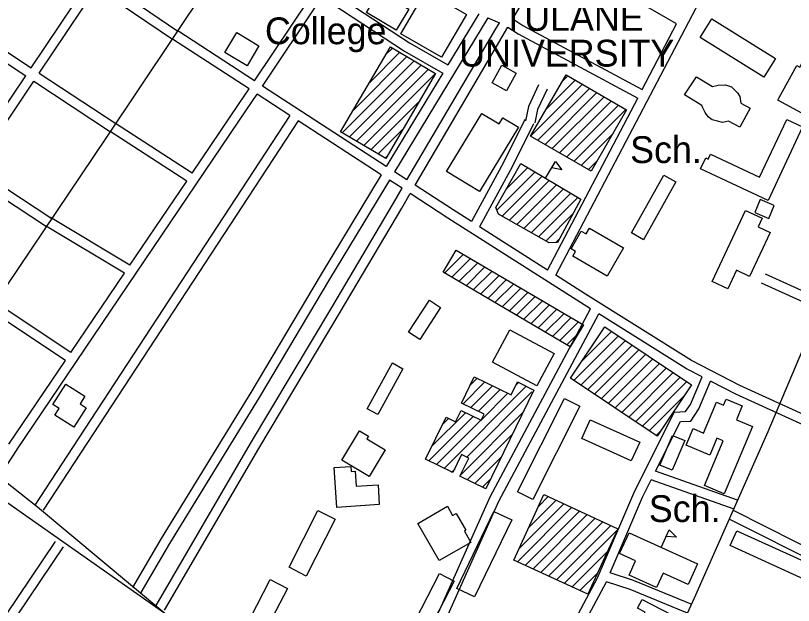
# Model space of a CAD drawing. Extents: x 3651524 to 3689615, y 505651 to 531377.
# Drawn here: x 3663276 to 3665685, y 524140 to 525966 of the extents above; entities that cross this region are included whole.
import ezdxf

# ---------------------------------------------------------------- set-up
doc = ezdxf.new("R2010")
doc.units = 0
for name, color, linetype in [('V-BLDG-IDEN', 7, 'Continuous'), ('V-BLDG-OTLN', 7, 'Continuous'), ('V-ROAD-CNTR', 7, 'Continuous')]:
    doc.layers.add(name, color=color, linetype=linetype)

msp = doc.modelspace()

# ---------------------------------------------------------------- linework, layer by layer
at = {"layer": 'V-BLDG-OTLN'}
for p, q in [((3664372.998, 525758.876), (3664465.933, 525851.811)), ((3664423.428, 525844.661), (3664443.667, 525864.9)), ((3664322.568, 525673.091), (3664488.199, 525838.721)), ((3664287.604, 525602.772), (3664510.465, 525825.632)), ((3664309.87, 525589.683), (3664532.731, 525812.543)), ((3664332.136, 525576.593), (3664554.997, 525799.453)), ((3664354.402, 525563.504), (3664577.263, 525786.364)), ((3664968.187, 525760.105), (3664987.017, 525778.935)), ((3664919.781, 525676.344), (3665009.424, 525765.986)), ((3664871.374, 525592.582), (3665031.83, 525753.037)), ((3664893.78, 525579.633), (3665054.237, 525740.088)), ((3664916.187, 525566.684), (3665076.643, 525727.14)), ((3664938.593, 525553.735), (3665099.049, 525714.191)), ((3664376.668, 525550.415), (3664526.832, 525700.579)), ((3664961, 525540.787), (3665121.456, 525701.243)), ((3664983.406, 525527.838), (3665143.862, 525688.294)), ((3665005.813, 525514.889), (3665166.269, 525675.345)), ((3664398.934, 525537.325), (3664476.401, 525614.792)), ((3665028.219, 525501.94), (3665124.55, 525598.271)), ((3664421.2, 525524.236), (3664425.97, 525529.006)), ((3664917.895, 525462.145), (3664948.648, 525513.665)), ((3665050.626, 525488.991), (3665076.143, 525514.509)), ((3664794.791, 525426.933), (3664862.857, 525494.998)), ((3664766.82, 525363.606), (3664884.996, 525481.783)), ((3664783.193, 525344.624), (3664907.136, 525468.567)), ((3664805.733, 525331.809), (3664929.276, 525455.351)), ((3664828.273, 525318.993), (3664951.416, 525442.136)), ((3664850.812, 525306.177), (3664973.555, 525428.92)), ((3664873.352, 525293.361), (3664995.695, 525415.705)), ((3664895.891, 525280.546), (3665017.835, 525402.489)), ((3664918.431, 525267.73), (3665002.335, 525351.634)), ((3664949.024, 525262.968), (3664961.746, 525275.689)), ((3664604.816, 525168.614), (3664663.039, 525226.837)), ((3664627.088, 525155.531), (3664685.312, 525213.754)), ((3664649.361, 525142.448), (3664707.584, 525200.671)), ((3664671.633, 525129.365), (3664729.856, 525187.588)), ((3664693.905, 525116.282), (3664752.128, 525174.505)), ((3664716.178, 525103.199), (3664774.4, 525161.422)), ((3664738.449, 525090.116), (3664796.673, 525148.339)), ((3664760.721, 525077.033), (3664818.945, 525135.256)), ((3664782.994, 525063.95), (3664841.217, 525122.173)), ((3664805.266, 525050.867), (3664863.49, 525109.09)), ((3664827.538, 525037.784), (3664885.762, 525096.007)), ((3664849.811, 525024.701), (3664908.034, 525082.924)), ((3664872.083, 525011.618), (3664930.307, 525069.841)), ((3664894.355, 524998.535), (3664952.579, 525056.758)), ((3664916.628, 524985.451), (3664974.851, 525043.675)), ((3664938.9, 524972.368), (3664997.124, 525030.592)), ((3664961.172, 524959.285), (3665019.396, 525017.509)), ((3665030.11, 524895.754), (3665122.704, 524988.347)), ((3664983.445, 524946.202), (3665018.827, 524981.585)), ((3665005.661, 524835.95), (3665143.889, 524974.177)), ((3665026.847, 524821.78), (3665165.075, 524960.008)), ((3665048.032, 524807.61), (3665186.26, 524945.838)), ((3665069.218, 524793.44), (3665207.446, 524931.668)), ((3665090.403, 524779.27), (3665228.631, 524917.498)), ((3665111.589, 524765.101), (3665249.816, 524903.328)), ((3665132.774, 524750.931), (3665271.001, 524889.158)), ((3665153.96, 524736.762), (3665292.187, 524874.989)), ((3664683.062, 524820.117), (3664706.116, 524843.171)), ((3665175.145, 524722.592), (3665313.372, 524860.819)), ((3665196.331, 524708.422), (3665334.558, 524846.649)), ((3664603.64, 524563.92), (3664857.902, 524818.182)), ((3664662.069, 524763.768), (3664729.889, 524831.588)), ((3664685.841, 524752.185), (3664753.66, 524820.005)), ((3664824.859, 524820.494), (3664834.13, 524829.764)), ((3665217.517, 524694.252), (3665355.743, 524832.479)), ((3664672.933, 524597.858), (3664875.579, 524800.505)), ((3664709.613, 524740.602), (3664777.432, 524808.422)), ((3664718.779, 524714.414), (3664801.205, 524796.839)), ((3665238.701, 524680.083), (3665346.956, 524788.337)), ((3664556.096, 524587.086), (3664693.652, 524724.642)), ((3664564.87, 524631.216), (3664669.88, 524736.225)), ((3664598.468, 524700.169), (3664617.13, 524718.83)), ((3664654.898, 524544.467), (3664848.08, 524737.649)), ((3664579.868, 524575.503), (3664717.425, 524713.059)), ((3665259.887, 524665.913), (3665275.548, 524681.575)), ((3664674.54, 524528.753), (3664814.486, 524668.7)), ((3664698.312, 524517.17), (3664780.891, 524599.75)), ((3664626.481, 524551.407), (3664637.824, 524562.749)), ((3664627.413, 524552.337), (3664634.439, 524559.363)), ((3664722.085, 524505.588), (3664747.297, 524530.8)), ((3664835.258, 524315.215), (3664974.301, 524454.257)), ((3664865.467, 524380.778), (3664950.097, 524465.409)), ((3664895.675, 524446.342), (3664925.894, 524476.561)), ((3664830.354, 524274.955), (3664998.504, 524443.105)), ((3664854.557, 524263.803), (3665022.708, 524431.954)), ((3664878.761, 524252.651), (3665046.912, 524420.802)), ((3664902.965, 524241.5), (3665071.115, 524409.65)), ((3664927.168, 524230.349), (3665095.319, 524398.498)), ((3664951.372, 524219.197), (3665119.522, 524387.347)), ((3664975.575, 524208.045), (3665138.812, 524371.281)), ((3665275.796, 524319.566), (3665300.631, 524374.185)), ((3664999.779, 524196.894), (3665108.603, 524305.717)), ((3665023.982, 524185.742), (3665078.395, 524240.153))]:
    msp.add_line(p, q, dxfattribs=at)
for points in [[(3664362.753, 525975.115), (3664441.117, 526107.503), (3664482.439, 526083.043), (3664469.611, 526061.371), (3664491.212, 526048.585), (3664464.15, 526002.865), (3664493.759, 525985.339), (3664455.286, 525920.343)], [(3664469.675, 525909.251), (3664546.359, 526041.824), (3664672.43, 525968.901), (3664595.746, 525836.328)], [(3665432.327, 525955.816), (3665630.093, 525832.936), (3665593.976, 525774.808), (3665396.21, 525897.687)], [(3664030.054, 525871.727), (3663993.385, 525810.404), (3663924.48, 525851.607), (3663961.149, 525912.93)], [(3665640.534, 525710.218), (3665695.623, 525810.695), (3665705.076, 525805.512), (3665764.153, 525913.261), (3665796.373, 525895.595), (3665751.975, 525814.62), (3665795.817, 525790.582), (3665722.676, 525657.182), (3665637.162, 525704.068)], [(3664577.263, 525786.364), (3664422.661, 525523.377), (3664282.867, 525605.557), (3664437.468, 525868.544)], [(3664826.877, 525787.165), (3664796.774, 525732.888), (3664752.04, 525757.697), (3664782.144, 525811.975)], [(3664871.374, 525592.582), (3664981.059, 525782.378), (3665168.385, 525674.122), (3665058.7, 525484.325)], [(3665384.98, 525776.167), (3665434.525, 525746.078), (3665452.36, 525750.688), (3665475.371, 525750.948), (3665493.77, 525744.599), (3665512.272, 525726.896), (3665519.741, 525715.191), (3665522.456, 525694.055), (3665551.791, 525679.399), (3665519.761, 525619.726), (3665484.089, 525638.867), (3665465.954, 525634.807), (3665450.26, 525638.731), (3665433.745, 525642.883), (3665421.638, 525652.098), (3665411.673, 525665.165), (3665403.313, 525681.72), (3665402.156, 525687.501), (3665348.017, 525720.117)], [(3664833.39, 525619.972), (3664712.793, 525421.22), (3664611.133, 525482.905), (3664720.129, 525662.537), (3664773.791, 525629.976), (3664785.392, 525649.096)], [(3665713.405, 525621.029), (3665606.667, 525393.264), (3665398.009, 525491.048), (3665413.863, 525524.878), (3665421.248, 525521.417), (3665428.244, 525536.345), (3665580.609, 525464.939), (3665664.502, 525643.948)], [(3664948.648, 525513.665), (3664968.487, 525488.37), (3664936.807, 525493.828)], [(3664840.717, 525508.214), (3665026.69, 525397.203), (3664955.093, 525263.242), (3664928.44, 525262.039), (3664772.374, 525350.776), (3664763.432, 525371.432)], [(3665183.915, 525292.66), (3665284.474, 525471.372), (3665321.515, 525450.529), (3665220.955, 525271.818)], [(3665625.889, 525377.915), (3665582.734, 525396.21), (3665565.616, 525355.832), (3665608.771, 525337.537)], [(3665434.155, 525142.08), (3665536.856, 525362.381), (3665588.444, 525338.332), (3665575.899, 525311.422), (3665612.93, 525294.159), (3665549.479, 525158.051), (3665508.715, 525177.054), (3665482.012, 525119.771)], [(3665158.911, 525246.743), (3665108.122, 525159.03), (3665002.028, 525220.461), (3665010.796, 525235.603), (3664996.511, 525243.874), (3665028.299, 525298.77), (3665043.823, 525289.781), (3665054.058, 525307.457)], [(3664640.767, 525239.919), (3665034.662, 525008.542), (3664994.298, 524939.827), (3664600.403, 525171.206)], [(3664493.224, 524985.119), (3664557.855, 525084.18), (3664592.49, 525061.583), (3664527.859, 524962.522)], [(3664806.736, 524993.084), (3664944.704, 524919.483), (3664891.136, 524819.068), (3664753.168, 524892.669)], [(3665101.518, 525002.517), (3665370.071, 524822.896), (3665263.47, 524663.516), (3664994.917, 524843.136)], [(3664365.258, 524748.662), (3664443.391, 524890.222), (3664476.067, 524872.187), (3664397.935, 524730.627)], [(3664881.675, 524806.599), (3664732.532, 524500.497), (3664652.479, 524539.502), (3664679.877, 524595.733), (3664657.478, 524606.647), (3664630.324, 524550.918), (3664545.81, 524592.098), (3664609.397, 524722.598), (3664639.037, 524708.156), (3664656.007, 524742.984), (3664717.986, 524712.786), (3664727.333, 524731.969), (3664656.846, 524766.313), (3664696.563, 524847.826), (3664811.007, 524792.063), (3664830.288, 524831.636)], [(3663391.504, 524761.599), (3663431.966, 524824.803), (3663490.963, 524787.034), (3663476.05, 524763.739), (3663494.601, 524751.863), (3663456.031, 524691.615), (3663398.045, 524728.736), (3663411.066, 524749.076)], [(3664830.713, 524491.758), (3664976.635, 524780.704), (3665023.897, 524756.836), (3664877.975, 524467.89)], [(3665558.185, 524693.361), (3665470.375, 524485.576), (3665409.596, 524511.261), (3665467.725, 524648.813), (3665448.222, 524657.055), (3665426.031, 524604.545), (3665352.923, 524635.441), (3665374.709, 524686.992), (3665406.898, 524673.388), (3665447.086, 524768.477), (3665468.877, 524759.267), (3665477.02, 524778.534), (3665526.863, 524757.468), (3665508.621, 524714.309)], [(3665056.027, 524714.419), (3665209.333, 524645.29), (3665183.249, 524587.443), (3665029.943, 524656.571)], [(3664371.649, 524538.604), (3664286.74, 524588.992), (3664340.891, 524680.242), (3664368.911, 524663.614), (3664363.945, 524655.247), (3664420.838, 524621.48)], [(3665271.994, 524574.468), (3665310.882, 524665.974), (3665348.729, 524649.89), (3665309.841, 524558.384)], [(3664402.637, 524451.817), (3664271.178, 524443.394), (3664263.292, 524566.466), (3664314.528, 524569.749), (3664315.511, 524554.413), (3664328.15, 524555.223), (3664331.146, 524508.472), (3664398.729, 524512.803)], [(3665048.186, 524174.59), (3664819.098, 524280.141), (3664912.452, 524482.754), (3665141.54, 524377.202)], [(3664265.97, 524406.921), (3664176.679, 524230.785), (3664123.287, 524257.851), (3664212.579, 524433.988)], [(3664686.08, 524334.813), (3664588.181, 524278.436), (3664521.749, 524393.796), (3664613.579, 524446.678), (3664629.891, 524418.352), (3664640.994, 524424.746), (3664671.155, 524372.372), (3664666.122, 524369.474)], [(3664812.741, 524404.481), (3664697.972, 524165.975), (3664643.158, 524192.352), (3664757.928, 524430.857)], [(3665176.216, 524364.847), (3665388.377, 524268.374), (3665359.448, 524204.754), (3665282.059, 524239.942), (3665261.523, 524194.779), (3665176.315, 524233.523), (3665196.663, 524278.273), (3665147.098, 524300.81)], [(3665300.631, 524374.185), (3665323.159, 524351.252), (3665291.069, 524353.155)], [(3665509.858, 524371.153), (3665740.579, 524266.248), (3665719.667, 524220.255), (3665488.946, 524325.16)], [(3664477.73, 524022.353), (3664589.017, 524238.4), (3664634.486, 524214.98), (3664523.2, 523998.932)], [(3663981.64, 524059.346), (3664065.105, 524220.129), (3664118.105, 524192.616), (3664034.641, 524031.833)], [(3665216.905, 524158.643), (3665306.652, 524111.308), (3665287.087, 524074.213), (3665220.59, 524109.286), (3665225.886, 524119.328), (3665202.637, 524131.589)]]:
    msp.add_lwpolyline(points, close=True, dxfattribs=at)
at = {"layer": 'V-ROAD-CNTR'}
for points in [[(3662939.923, 524671.627), (3663556.362, 525585.991), (3664184.93, 526525.227), (3664593.526, 527125.754), (3664954.368, 527669.074), (3665094.157, 527888.096), (3665238.971, 528097.362)], [(3663344.161, 524443.476), (3662896.215, 524797.415), (3661850.172, 525702.548), (3660405.103, 527021.233), (3660409.707, 527021.285)], [(3664816.386, 525955.444), (3664937.997, 526163.352)], [(3665323.671, 525940.281), (3664937.997, 526163.352)], [(3663324.139, 525804.175), (3663502.326, 526069.2)], [(3663543.877, 526077.235), (3663778.525, 525917.767)], [(3664945.209, 523148.69), (3665042.624, 523378.544), (3665238.697, 523856.758), (3665379.161, 524163.771), (3665607.436, 524678.567), (3666116.156, 525881.117), (3666199.736, 526079.228)], [(3664949.571, 525161.67), (3665425.981, 526070.9)], [(3663349.183, 525787.656), (3663527.138, 526052.337)], [(3663527.138, 526052.338), (3663761.663, 525892.955)], [(3664242.479, 526048.579), (3664496.517, 525880.795), (3664615.196, 525813.284)], [(3664015.801, 525763.685), (3664190.456, 526024.665), (3664200.794, 526040.158)], [(3664040.963, 525747.344), (3664215.398, 526007.997), (3664225.827, 526023.624)], [(3664225.827, 526023.625), (3664480.817, 525855.213), (3664599.645, 525787.616)], [(3663108.006, 525947.838), (3663294.965, 525823.42), (3663324.139, 525804.176)], [(3664738.466, 525958.86), (3664449.57, 525482.001)], [(3664710.652, 525970.845), (3664615.196, 525813.284)], [(3664738.466, 525958.86), (3664774.537, 525943.317)], [(3664816.386, 525955.444), (3664847.645, 525934.955), (3665217.037, 525736.768)], [(3664488.461, 525456.744), (3664763.324, 525924.148), (3664774.537, 525943.317)], [(3664513.645, 525440.388), (3664801.266, 525929.485)], [(3664801.266, 525929.485), (3664832.301, 525909.143), (3665203.112, 525710.194)], [(3665217.037, 525736.768), (3665323.671, 525940.281)], [(3663092.178, 525922.336), (3663278.395, 525798.41), (3663307.4, 525779.279)], [(3664015.803, 525763.685), (3663778.263, 525917.941)], [(3663999.116, 525738.75), (3663761.925, 525892.781)], [(3663174.157, 525581.1), (3663307.4, 525779.278)], [(3663349.183, 525787.657), (3663586.462, 525631.148)], [(3664599.646, 525787.616), (3664424.397, 525498.347)], [(3663199.053, 525564.362), (3663332.444, 525762.759)], [(3663332.443, 525762.76), (3663569.944, 525606.106)], [(3663822.894, 525477.867), (3663968.968, 525693.704), (3663999.115, 525738.751)], [(3664424.398, 525498.347), (3664040.965, 525747.345)], [(3664895.834, 525750.817), (3664864.476, 525684.07), (3664855.101, 525639.266)], [(3664922.986, 525738.061), (3664893.122, 525674.49), (3664884.465, 525633.122)], [(3663279.758, 524621.809), (3663993.856, 525676.954), (3664024.277, 525722.411)], [(3664125.767, 525656.505), (3664024.278, 525722.411)], [(3664924.165, 525177.821), (3665203.112, 525710.194)], [(3664125.767, 525656.506), (3663452.871, 524629.035), (3663335.326, 524450.129)], [(3664150.927, 525640.167), (3663361.134, 524434.199)], [(3664408.846, 525472.676), (3664150.928, 525640.166)], [(3664853.424, 525644.326), (3664787.258, 525511.223), (3664688.112, 525327.873)], [(3663822.896, 525477.868), (3663585.701, 525631.65)], [(3664880.288, 525630.972), (3664813.892, 525497.407), (3664713.493, 525311.739)], [(3663806.078, 525453.019), (3663569.381, 525606.478)], [(3663150.958, 525493.272), (3663388.655, 525337.59)], [(3663134.145, 525468.422), (3663372.219, 525312.494)], [(3664408.845, 525472.677), (3664222.26, 525164.693), (3664004.914, 524799.167), (3663727.49, 524347.013), (3663638.312, 524195.263)], [(3664488.462, 525456.744), (3664449.57, 525482)], [(3663629.924, 525192.735), (3663806.077, 525453.018)], [(3664434.018, 525456.331), (3664247.981, 525149.255), (3664030.594, 524783.655), (3663753.209, 524331.567), (3663664.176, 524180.063)], [(3664473.24, 525430.858), (3664434.018, 525456.329)], [(3663711.613, 524140.002), (3664003.596, 524641.158), (3664255.744, 525062.408), (3664446.245, 525384.957), (3664473.239, 525430.859)], [(3664688.113, 525327.872), (3664631.263, 525364.01), (3664513.646, 525440.389)], [(3663737.534, 524124.9), (3664029.428, 524625.902), (3664281.53, 525047.076), (3664472.091, 525369.725), (3664498.423, 525414.503)], [(3665057.197, 525058.051), (3665025.44, 525077.896), (3664615.047, 525338.77), (3664498.425, 525414.504)], [(3663629.925, 525192.734), (3663384.03, 525340.607)], [(3663613.086, 525167.854), (3663368.57, 525314.897)], [(3664924.166, 525177.821), (3664713.494, 525311.738)], [(3663447.17, 524922.699), (3663613.085, 525167.854)], [(3665929.514, 524633.91), (3665519.744, 524820.417), (3665369.302, 524898.389), (3665041.436, 525103.276), (3664949.572, 525161.671)], [(3666063.417, 524954.985), (3665598.744, 525164.847)], [(3666051.771, 524927.328), (3665586.396, 525137.507)], [(3663447.171, 524922.7), (3663208.788, 525080.473)], [(3664357.365, 523607.25), (3664746.402, 524475.782), (3665057.195, 525058.051)], [(3663430.356, 524897.854), (3663192.23, 525055.455)], [(3664384.743, 523594.986), (3664773.356, 524462.572), (3665082.695, 525042.116)], [(3665402.279, 524847.507), (3665354.426, 524872.309), (3665082.696, 525042.116)], [(3663254.914, 524638.623), (3663430.355, 524897.853)], [(3665539.423, 523630.346), (3665486.7, 523651.8), (3665315.189, 523736.929), (3665242.377, 523767.331), (3664916.844, 523921.124), (3665078.944, 524225.288), (3665190.662, 524487.11), (3665316.324, 524738.224), (3665351.14, 524739.583), (3665366.148, 524762.098), (3665402.278, 524847.508)], [(3665258.587, 524555.811), (3665335.216, 524708.939), (3665367.61, 524710.204), (3665392.678, 524747.808), (3665428.994, 524833.661)], [(3665918.605, 524605.914), (3665506.62, 524793.429), (3665428.995, 524833.661)], [(3663279.869, 524621.975), (3663057.146, 524283.236), (3662882.634, 524020.742)], [(3665511.828, 524465.754), (3665258.589, 524555.812)], [(3665118.215, 524240.881), (3665217.898, 524474.498), (3665245.061, 524528.782)], [(3665501.776, 524437.488), (3665245.062, 524528.782)], [(3663738.632, 524114.863), (3663202.07, 524489.981)], [(3663738.632, 524114.863), (3663344.161, 524443.476)], [(3665793.764, 524285.51), (3665499.606, 524433.583)], [(3665776.104, 524260.813), (3665486.118, 524406.787)], [(3663090.557, 523880.402), (3663399.811, 524338.19)], [(3663030.326, 523737.65), (3663424.671, 524321.396)], [(3665369.097, 524143.211), (3665189.875, 524216.723), (3665118.215, 524240.882)], [(3665550.251, 523658.328), (3665499.04, 523679.168), (3665327.651, 523764.235), (3665254.571, 523794.749), (3664958.126, 523934.8), (3665106.028, 524212.322), (3665106.405, 524213.205)], [(3665357.713, 524115.455), (3665179.379, 524188.603), (3665106.406, 524213.205)]]:
    msp.add_lwpolyline(points, dxfattribs=at)

# ---------------------------------------------------------------- texts
at = {"layer": 'V-BLDG-IDEN'}
for s, p in [('TULANE', (3664783.681, 525918.437)), ('College', (3664048.469, 525876.908)), ('UNIVERSITY', (3664650.331, 525807.702)), ('Sch.', (3665179.642, 525509.1)), ('Sch.', (3665237.564, 524397.906))]:
    msp.add_text(s, height=82.9998, dxfattribs=at).set_placement(p)

doc.saveas('drawing.dxf')
